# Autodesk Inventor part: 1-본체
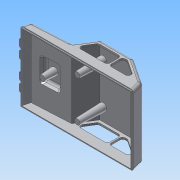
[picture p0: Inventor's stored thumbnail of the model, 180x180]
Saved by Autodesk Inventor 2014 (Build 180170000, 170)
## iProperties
Created: 2015-05
Part Number: 1-본체
Material: ABS 플라스틱
Document SubType Name: Modeling
Designer: Administrator
Density: 1.06 g/cm^3
Appearance: 매끄러움 - 흰색
Mass: 33.5817 g
Surface Area: 321.412 cm^2
Volume: 31.6809 cm^3
Author: Administrator
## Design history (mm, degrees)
sketch "스케치1"
  geometry: L1 (-61, 0)-(61, 0); L2 (-61, 0)-(-58.588, 9); L3 (-16.588, 11.201)-(-4.842, 30); L4 (61, 30)-(61, 0); L5 (-58.588, 9)-(-16.588, 11.201); L6 (-4.842, 30)-(61, 30); 3 further points
  constraints: 12 end point, 2 coincident, 1 horizontal, 1 midpoint, 1 parallel, 1 perpendicular
  dimensions: "d11" = 122 distance of L1.start L1.end; "d12" = 30 distance of L4.start L1.end; "d14" = 105 deg angle of L1 L2; "d16" = 3 deg angle of L1 L5; "d17" = 125 deg angle of L3 L5; "d18" = 42 horizontal distance of L2.end L3.start; "d19" = 9 vertical distance of L1.start L2.end
extrude "돌출1" new body sketch "스케치1" distance "d20" = 76; taper "d21" = 0 deg
sketch "스케치2"
  geometry: L1 (61, 30)-(-4.842, 30) reference; L2 (61, 30)-(31, 30); L3 (31, 30)-(61, 10); L4 (61, 10)-(61, 30); 1 further point
  constraints: 6 end point, 1 perpendicular, 1 point on line
  dimensions: "d22" = 30 distance of L1.start L2.end; "d23" = 20 distance of L3.end L1.start
extrude "돌출2" cut sketch "스케치2" stored distance "d24" = 76; taper "d25" = 0 deg
sketch "스케치3"
  geometry: L1 (61, 10)-(31, 30) reference; L2 (61, 0)-(61, 10) reference; L3 (61, 0)-(57.738, 12.175); L4 (61, 0)-(73.738, 0); 1 further point
  constraints: 4 end point, 1 perpendicular, 1 point on line
  dimensions: "d26" = 105 deg angle of L4 L3
extrude "돌출3" cut sketch "스케치3" stored distance "d27" = 76; taper "d28" = 0 deg
feature "쉘1" dims "d29" = 2
sketch "스케치4"
  geometry: L1 (119.929, 74)-(119.929, 2) reference; L2 (119.929, 2)-(2.071, 2) reference; L3 (2.071, 2)-(2.071, 74) reference; L4 (2.071, 74)-(119.929, 74) reference; L5 (0, 0)-(122, 0) reference; L6 (122, 0)-(122, 76) reference; L7 (0, 76)-(122, 76) reference; L8 (0, 0)-(0, 76) reference; L9 (121, 75)-(121, 1); L10 (121, 1)-(1, 1); L11 (1, 1)-(1, 75); L12 (1, 75)-(121, 75); 1 further point
  constraints: 8 end point, 3 other
  dimensions: "d30" = 1 distance between parallel lines of L12 L7
extrude "돌출4" join sketch "스케치4" distance "d31" = 1; taper "d32" = 0 deg
sketch "스케치5"
  geometry: L1 (57.738, 12.175)-(31, 30) reference; L2 (31, 30)-(-4.842, 30) reference; L3 (-4.842, 30)-(-16.588, 11.201) reference; L4 (-11.443, 10)-(-2.07, 25); L5 (-2.07, 25)-(29.486, 25); L6 (29.486, 25)-(51.986, 10); L7 (-11.443, 10)-(22.557, 10); L8 (22.557, 10)-(22.557, 25); L9 (51.986, 10)-(23.986, 10); L10 (23.986, 10)-(23.986, 25); 1 further point
  constraints: 14 end point, 3 perpendicular, 2 point on line, 1 collinear, 1 parallel, 2 other
  dimensions: "d33" = 5 distance between parallel lines of L5 L2; "d34" = 34 distance of L4.start L7.end; "d35" = 15 distance of L7.end L8.end; "d36" = 28 distance of L6.end L9.end
extrude "돌출5" cut sketch "스케치5" stored distance "d37" = 1; taper "d38" = 0 deg
fillet "모깎기1" dims "d39" = 3
node "작업 평면1"
node "작업 평면2"
sketch "스케치6"
  geometry: L1 (11, 51)-(31, 51); L2 (31, 51)-(31, 25); L3 (31, 25)-(11, 25); L4 (11, 25)-(11, 51); L5 (11, 51)-(31, 25); L6 (31, 51)-(11, 25); L7 (0, 76)-(0, 0) reference; 4 further points
  constraints: 12 end point, 4 midpoint, 2 parallel, 1 horizontal, 1 horizontal alignment, 1 perpendicular
  dimensions: "d41" = 20 distance of L1.start L1.end; "d42" = 26 distance of L1.end L2.end; "d43" = 11 distance between parallel lines of L4 L7
extrude "돌출6" join sketch "스케치6" stored distance "d44" = 1; taper "d45" = 20 deg
node "작업 평면4"
  node "작업 평면3"
sketch "스케치7"
  geometry: L1 (0, 38)-(-67.522, 38); A1 r 4 centre (0, 48) between (0, 52) and (0, 44); A2 r 4 centre (0, 59) between (0, 63) and (0, 55); A3 r 4 centre (0, 28) between (0, 32) and (0, 24); A4 r 4 centre (0, 17) between (0, 21) and (0, 13); 2 further points
  constraints: 8 point on circle, 4 centre point, 3 equal radius, 2 end point, 1 horizontal, 14 other
  dimensions: "d48" = 10 distance from line of A1.centre L1; "d49" = 11 distance of A2.centre A1.centre; "d50" = 4 radius of A1; "d51" = 20 distance of A1.centre A3.centre; "d52" = 11 distance of A3.centre A4.centre
extrude "돌출7" join sketch "스케치7" stored distance "d53" = 1; taper "d54" = 0 deg
sketch "스케치9"
  geometry: L1 (9.18, 23.18)-(9.18, 52.82) reference; L2 (9.18, 52.82)-(32.82, 52.82) reference; L3 (32.82, 52.82)-(32.82, 23.18) reference; L4 (32.82, 23.18)-(9.18, 23.18) reference; L5 (30.82, 25.18)-(30.82, 50.82); L6 (30.82, 50.82)-(11.18, 50.82); L7 (11.18, 50.82)-(11.18, 25.18); L8 (11.18, 25.18)-(30.82, 25.18); 1 further point
  constraints: 8 end point, 3 other
  dimensions: "d57" = 2 distance between parallel lines of L3 L5
extrude "돌출8" cut sketch "스케치9" distance "d58" = 3; taper "d59" = -20 deg; dims "d60" = 20, "d61" = 20 deg
node "작업 평면6"
sketch "스케치10"
  geometry: L1 (31.942, 49.728)-(14.51, 49.728) reference; L2 (14.51, 49.728)-(14.51, 26.272) reference; L3 (14.51, 26.272)-(31.942, 26.272) reference; L4 (31.942, 26.272)-(31.942, 49.728) reference; L5 (23.226, 49.728)-(23.226, 26.272); L6 (34.021, 51.548)-(34.021, 24.452) reference; L7 (34.021, 38)-(14.51, 38); C1 r 3 at (23.226, 38); 1 further point
  constraints: 5 midpoint, 4 end point, 1 centre point, 1 perpendicular, 1 point on line
  dimensions: "d67" = 6 diameter of C1
  node "투영된 루프1"
extrude "돌출10" join sketch "스케치10" stored distance "d68" = 3; taper "d69" = 4 deg
node "작업 평면10"
  node "작업축1"
node "작업 평면11"
sketch "스케치12"
  geometry: L1 (122, 0)-(122, 76) reference; L2 (0, 76)-(122, 76) reference; L3 (-11.148, 38)-(144.465, 38); C1 r 3 at (61, 16); C2 r 3 at (61, 60); 1 further point
  constraints: 2 centre point, 2 end point, 1 equal radius, 1 perpendicular, 1 vertical alignment
  dimensions: "d87" = 6 diameter of C2; "d88" = 61 distance from line of L1 C2.centre; "d89" = 38 distance between parallel lines of L3 L2; "d90" = 22 distance from line of L3 C2.centre; "d91" = 44 distance of C1.centre C2.centre
extrude "돌출12" join sketch "스케치12" stored distance "d92" = 2; taper "d93" = 2 deg
fillet "모깎기2" dims "d94" = 3
fillet "모깎기3" dims "d95" = 3
chamfer "모따기1" distance "d96" = 1; stored, may be unused: second distance "d97" = 2, angle "d98" = 45 deg
sketch "스케치13"
  geometry: L1 (64.179, 0)-(64.179, -70) reference; 3 further points
  constraints: 1 horizontal alignment, 1 midpoint, 1 other
  dimensions: "d99" = 50 distance from line of L1 point (14.179, -35)
feature "엠보싱1" sketch "스케치13" dims "d100" = 0.5, "d101" = 0
node "솔리드1"
mirror "대칭1"
other parameters: "d40" = 5, "d46" = 0, "d47" = 2, "d62" = 0, "d72" = 0, "d86" = 0
